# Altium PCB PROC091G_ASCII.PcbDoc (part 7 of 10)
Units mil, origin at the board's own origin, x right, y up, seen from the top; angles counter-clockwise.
Board outline 4538.11 x 994.94 mil, 8 copper layers (Top Layer, GND1, Sig1, PWR1, PWR2, Sig2, GND2, Bottom Layer), stack 59.155 mil thick; 447 components, 329 nets, 5050 pads, 868 vias.
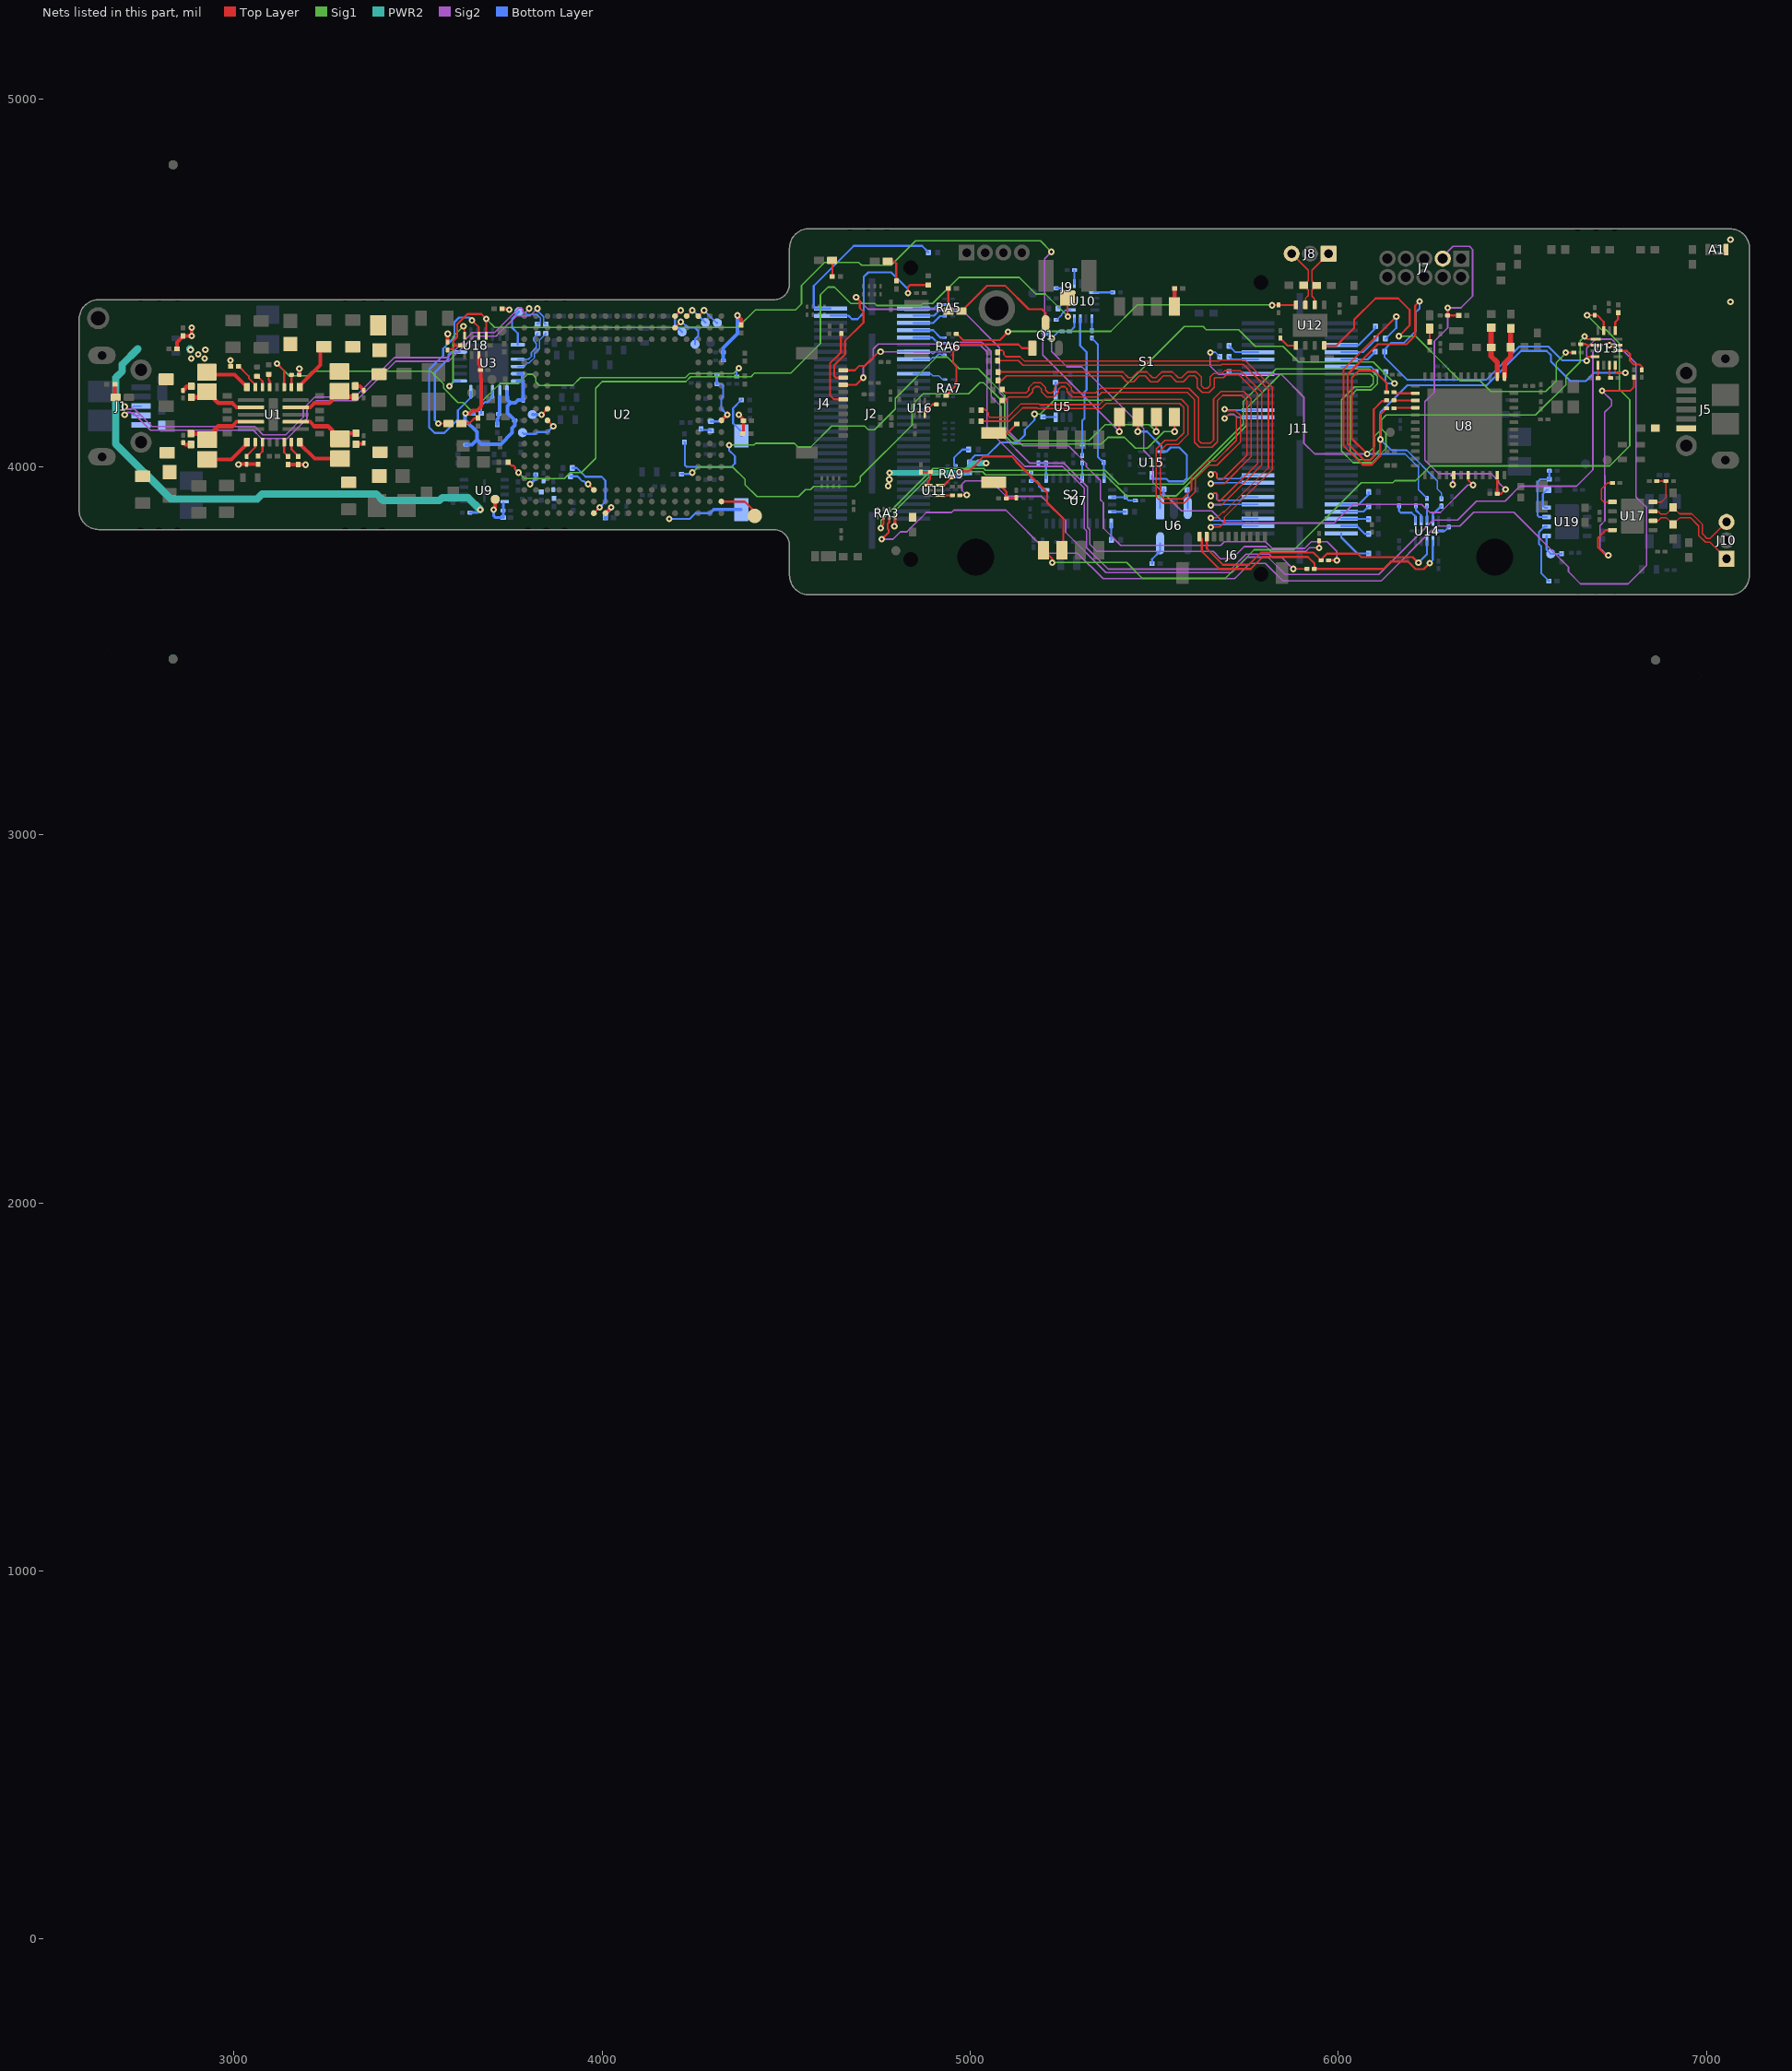
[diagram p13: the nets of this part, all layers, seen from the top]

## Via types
v1: diameter 18, hole 8, Top Layer to Bottom Layer, tented both sides, 832 vias
v2: diameter 19.68, hole 7.87, Top Layer to Bottom Layer, tented both sides, 34 vias
v3: diameter 17, hole 7.87, Top Layer to Bottom Layer, tented both sides, 1 vias
v4: diameter 17, hole 8, Top Layer to Bottom Layer, tented both sides, 1 vias

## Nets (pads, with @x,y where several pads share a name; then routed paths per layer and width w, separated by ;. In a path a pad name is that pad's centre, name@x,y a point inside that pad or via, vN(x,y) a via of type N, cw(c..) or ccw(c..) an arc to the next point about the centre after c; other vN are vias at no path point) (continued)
NetJ2_42: J2.42 RA7.4 | length 92
  Bottom Layer w4: J2.42@4846.16,4252.77 4892.84,4252.77 4898.97,4246.64 4915.49,4246.64 4924.86,4237.27 RA7.4@4931.69,4237.27
NetJ2_46: J2.46 RA6.1 | length 90.9
  Bottom Layer w4: J2.46@4846.16,4292.14 4892.84,4292.14 4897.18,4296.48 4904.46,4296.48 4914.12,4306.15 4919.89,4306.15 4922.26,4303.77 RA6.1@4930.26,4303.77
NetJ2_48: J2.48 RA6.2 | length 90.9
  Bottom Layer w4: J2.48@4846.16,4311.82 4892.84,4311.82 4897.18,4307.48 4899.9,4307.48 4903.44,4311.02 4909.57,4317.15 4919.89,4317.15 4922.26,4319.52 RA6.2@4930.26,4319.52
NetJ2_52: J2.52 RA6.3 | length 90.7
  Bottom Layer w5.5: J2.52@4846.16,4351.19 4897.66,4351.19 4913.58,4335.27 RA6.3@4930.26,4335.27
NetJ2_54: J2.54 RA6.4 | length 92.3
  Bottom Layer w5.5: J2.54@4846.16,4370.88 4899.09,4370.88 4918.95,4351.02 RA6.4@4930.26,4351.02
NetJ2_56: J2.56 RA5.1 | length 92.2
  Bottom Layer w5.5: J2.56@4846.16,4390.56 4899.25,4390.56 4917.78,4409.09 RA5.1@4930.68,4409.09
NetJ2_57: J2.57 R14.1 | length 428.2
  Top Layer w5.5: v1(4831,4471.63) 4831,4488.23 4836.24,4493.46 R14.1@4886,4493.46
  Bottom Layer w5.5: J2.57@4620.57,4410.25 4669.54,4410.25 4678.95,4400.84 4693.94,4400.84 4711.09,4417.99 4711.09,4516 4723.3,4528.21 4785.55,4528.21 4831,4482.76 v1(4831,4471.63)
NetJ2_58: J2.58 RA5.2 | length 90.6
  Bottom Layer w5.5: J2.58@4846.16,4410.25 4901.51,4410.25 4916.1,4424.84 RA5.2@4930.68,4424.84
NetJ2_59: J2.59 R12.1 | length 468.6
  Bottom Layer w5.5: J2.59@4620.57,4429.93 4579.07,4429.93 4575,4434 4575,4491 4684.01,4600.01 4869.23,4600.01 4886.18,4583.06 R12.1@4886.18,4582.07
NetJ2_60: J2.60 RA5.3 | length 88.9
  Bottom Layer w5.5: J2.60@4846.16,4429.93 4901.9,4429.93 4912.56,4440.59 RA5.3@4930.68,4440.59
NetJ4_1: J4.1 R185.2 | length 1787
  Top Layer w4.2: v1(5877.52,3722.34) 5877.68,3722.49 R185.2@5915.32,3722.49
  Top Layer w5.5: J4.1@4655.33,4261.92 4686.74,4261.92 4699.09,4274.27 4713.5,4274.27 4751.62,4312.39 v1(4756.43,4312.39)
  Sig2 w4.2: v1(4756.43,4312.39) 4945.94,4312.39 4963.54,4329.99 5028.14,4329.99 5046.11,4312.02 5046.11,4103.61 5148.58,4001.15 5251.09,4001.15 5310.09,3942.14 5310.09,3831.93 5316.31,3825.72 5316.31,3780.32 5374.82,3721.81 5708.67,3721.81 5749.48,3762.62 5812.52,3762.62 5820.92,3754.22 5845.64,3754.22 v1(5877.52,3722.34)
NetJ4_2: J4.2 R184.2 | length 2138.7
  Top Layer w5.5: J4.2@4655.33,4242.23 4634.63,4242.23 4630.69,4246.17 4630.69,4275.86 4660.18,4305.35 4660.18,4341.86 4710,4391.68 4710,4421.45 4700,4431.45 4700,4450.56 v1(4690.34,4460.22) ; R184.2@5973.37,3745.98 v1@5996.22,3745.98
  Sig2 w4.2: v1(4690.34,4460.22) 4722.61,4427.95 4975.45,4427.95 5080.01,4323.39 5080.01,4201.21 5100.76,4180.46 5100.76,4099.49 5143.46,4056.79 5267.6,4056.79 5315.85,4008.55 5315.85,4000.78 5353.67,3962.95 5353.67,3910.52 5362.07,3902.12 5362.07,3833.36 5408.84,3786.59 5680.29,3786.59 5690.37,3796.67 5802.23,3796.67 5820.8,3778.11 5908.27,3778.11 5926.79,3796.63 5970.1,3796.63 5996.34,3770.38 v1(5996.34,3745.86)
NetJ4_3: J4.3 R183.2 | length 1860.1
  Top Layer w5.5: J4.3@4655.33,4222.55 4690.14,4222.55 v1(4709.72,4242.13) ; v1(5947.68,3779.72) R183.2@5947.68,3798.4
  Sig2 w4.2: v1(4709.72,4242.13) 4709.72,4269.52 4736.36,4296.16 4736.36,4319.64 4750.21,4333.49 4955.16,4333.49 4960.06,4338.39 5031.61,4338.39 5056.94,4313.07 5056.94,4190.97 5083.96,4163.95 5083.96,4087.47 5161.87,4009.55 5254.56,4009.55 5318.49,3945.62 5318.49,3835.41 5324.71,3829.2 5324.71,3789.37 5344.29,3769.79 5660.31,3769.79 5680.02,3750.08 5711.21,3750.08 5744.21,3783.09 5803.94,3783.09 5817.32,3769.71 5911.75,3769.71 5921.77,3779.72 v1(5947.68,3779.72)
NetJ4_5: J4.5 R182.2 | length 220.1
  Top Layer w5.5: R182.2@4650.14,4360.81 4648.68,4359.35 4648.68,4310.11 4619.19,4280.63 4619.19,4194.32 4630.34,4183.18 J4.5@4655.33,4183.18
NetJ8_1: J8.1 R126.1 U12.6 | length 171.7
  Top Layer w4: U12.6@5936.23,4439.58 5936.23,4455.71 5928.49,4463.46 5928.49,4479.74 R126.1@5941.23,4492.48 5928.49,4505.23 5928.49,4533.93 J8.1@5973.44,4578.88
NetJ8_3: J8.3 R119.2 U12.7 | length 171.7
  Top Layer w4: J8.3@5873.44,4578.88 5918.39,4533.93 5918.39,4505.52 R119.2@5905.64,4492.77 5918.39,4480.03 5918.39,4464.68 5910.64,4456.94 U12.7@5910.64,4439.58
NetJ9_1: J9.1 R109.2 | length 2093.9
  Top Layer w5.5: R109.2@3744.93,4012.38 3754.32,4003 3759.5,4003 3763.64,3998.86 3763.64,3993.5 v1(3773.02,3984.13) ; J9.1@5264.12,4458.32 5264.12,4409.45 v1(5265.4,4408.17)
  Sig1 w4.2: v1(3773.02,3984.13) 3789.15,3968 3897.5,3968 3913.75,3984.25 3944.25,3984.25 3982.78,4022.78 3982.78,4213.56 4000.43,4231.21 4227.66,4231.21 4241.04,4244.59 4404.59,4244.59 4414.28,4254.28 4512.93,4254.28 4593,4334.35 4593,4467 4614,4488 4631.2,4488 4675.95,4443.25 4740.74,4443.25 4745.91,4438.08 4865.87,4438.08 4871.09,4443.3 4898.45,4443.3 4969.66,4514.51 5133.53,4514.51 5178.56,4469.48 5204.09,4469.48 v1(5265.4,4408.17)
NetJ10_1: J10.1 R117.1 U17.6 | length 279.7
  Top Layer w4: U17.6@6854.9,3853.2 6868.71,3853.2 6876.46,3860.95 6891.92,3860.95 R117.1@6909.66,3843.2 6928.28,3861.82 6956.61,3861.82 6979.41,3839.02 6979.41,3813.1 6997.56,3794.95 7009.86,3794.95 J10.1@7054.81,3750
NetJ10_3: J10.3 R114.2 U17.7 | length 279.6
  Top Layer w4: U17.7@6854.9,3878.8 6868.71,3878.8 6876.46,3871.05 6891.02,3871.05 R114.2@6909.57,3889.61 6927.26,3871.92 6934.39,3871.92 6960.79,3871.92 6989.51,3843.2 6989.51,3817.28 7001.74,3805.05 7009.86,3805.05 J10.3@7054.81,3850
NetJ11_7: J11.7 R150.1 | length 117.4
  Bottom Layer w5.5: J11.7@6007.91,4330.88 6055.82,4330.88 6100.82,4375.88 R150.1@6100.82,4381.76
NetJ11_9: J11.9 R151.1 | length 111.5
  Bottom Layer w5.5: J11.9@6007.91,4311.19 6067.59,4311.19 6102.62,4346.22 R151.1@6102.62,4348.48
NetJ11_10: J11.10 R152.2 | length 85.7
  Bottom Layer w5.5: R152.2@5703.72,4328.4 5720.93,4311.19 J11.10@5782.32,4311.19
NetJ11_11: J11.11 R153.1 | length 101.3
  Bottom Layer w5.5: J11.11@6007.91,4291.51 6079.44,4291.51 R153.1@6100.53,4312.59
NetJ11_12: J11.12 R154.2 | length 81.7
  Bottom Layer w5.5: R154.2@5703.72,4298.93 5711.14,4291.51 J11.12@5782.32,4291.51
NetJ11_13: J11.13 R155.1 | length 100.7
  Bottom Layer w5.5: J11.13@6007.91,4271.82 6088.51,4271.82 R155.1@6102.76,4257.57
NetJ11_16: J11.16 R157.2 | length 80.9
  Bottom Layer w5.5: R157.2@5703.72,4257.72 5709.31,4252.14 J11.16@5782.32,4252.14
NetJ11_26: J11.26 R142.2 | length 1406.7
  Top Layer w4: R142.2@5029.87,4123.69 5106.17,4123.69 5142.59,4160.12 5181.65,4160.12 5183.99,4157.77 5355.15,4157.77 5369.44,4172.06 5569.36,4172.06 5580.3,4161.12 5580.3,4091.79 5560.01,4071.51 5529.19,4071.51 5505.39,4047.7 5505.39,3918.62 5522.21,3901.79 5581.54,3901.79 5612.17,3932.43 5612.17,3967.43 5648.64,4003.9 5670.59,4003.9 5734.2,4067.51 5734.2,4139.44 5722.14,4151.51 5696.52,4151.51 v1(5691.66,4156.37)
  Bottom Layer w4: v1(5691.66,4156.37) 5694.31,4153.71 J11.26@5782.32,4153.71
NetJ11_28: J11.28 R143.2 | length 1394.2
  Top Layer w4: R143.2@5029.87,4153.69 5033.06,4156.88 5038.48,4156.88 5048.87,4146.48 5048.87,4138.92 5053.1,4134.69 5101.61,4134.69 5129.25,4162.33 5138.04,4171.12 5186.2,4171.12 5188.55,4168.77 5350.59,4168.77 5364.88,4183.06 5573.92,4183.06 5591.3,4165.68 5591.3,4087.24 5564.57,4060.51 5533.75,4060.51 5516.39,4043.14 5516.39,3923.17 5526.77,3912.79 5576.98,3912.79 5601.17,3936.98 5601.17,3971.98 5644.09,4014.9 5666.03,4014.9 5723.2,4072.07 5723.2,4134.89 5717.58,4140.51 5700.79,4140.51 v1(5691.66,4131.37)
  Bottom Layer w4: v1(5691.66,4131.37) 5703,4142.71 5717.1,4142.71 5725.78,4134.03 J11.28@5782.32,4134.03
NetJ11_44: J11.44 R144.2 | length 1442.9
  Top Layer w4: R144.2@5087.73,4180.12 5090.98,4176.88 5096.57,4176.88 5101.19,4181.5 5101.19,4185.67 5105.14,4189.62 5156.29,4189.62 5170.01,4203.34 5170.01,4210.43 5177.29,4217.71 5186.73,4217.71 5194.01,4210.43 5194.01,4203.34 5207.73,4189.62 5226.29,4189.62 5240.01,4203.34 5240.01,4210.43 5247.29,4217.71 5256.73,4217.71 5264.01,4210.43 5264.01,4203.34 5277.73,4189.62 5345.19,4189.62 5357.68,4202.11 5589.59,4202.11 5609.3,4182.4 5609.3,4066.81 5623.19,4052.92 5657.16,4052.92 5672.13,4067.89 5672.13,4179.83 5686.05,4193.75 5738.48,4193.75 5752.25,4179.98 5752.25,4031.61 5685.85,3965.2 5673.82,3965.2 5669.23,3969.8 5669.23,3982.18 5665.52,3985.9 5660.36,3985.9 v1(5653.67,3979.2)
  Bottom Layer w4: v1(5653.67,3979.2) 5660.23,3985.77 5665.46,3985.77 5669.23,3982 5669.23,3971.01 5672.38,3967.86 5732.95,3967.86 5741.64,3976.55 J11.44@5782.32,3976.55
NetJ11_46: J11.46 R145.2 | length 1436.5
  Top Layer w4: R145.2@5087.73,4210.12 5097.23,4200.62 5151.73,4200.62 5159.01,4207.9 5159.01,4214.99 5172.73,4228.71 5191.29,4228.71 5205.01,4214.99 5205.01,4207.9 5212.29,4200.62 5221.73,4200.62 5229.01,4207.9 5229.01,4214.99 5242.73,4228.71 5261.29,4228.71 5275.01,4214.99 5275.01,4207.9 5282.29,4200.62 5340.63,4200.62 5353.12,4213.11 5594.15,4213.11 5620.3,4186.96 5620.3,4071.37 5627.75,4063.92 5652.6,4063.92 5661.13,4072.45 5661.13,4184.38 5681.5,4204.75 5743.04,4204.75 5763.25,4184.53 5763.25,4102.24 5763.25,4035.73 5763.25,4027.05 5690.4,3954.2 v1(5653.67,3954.2)
  Bottom Layer w4: v1(5653.67,3954.2) 5656.32,3956.86 J11.46@5782.32,3956.86
NetJ11_50: J11.50 R146.2 | length 1368.9
  Top Layer w4: R146.2@5075.6,4234.19 5086.07,4234.19 5098.59,4246.71 5409.93,4246.71 5425.53,4231.1 5444.09,4231.1 5459.69,4246.71 5475.03,4246.71 5490.63,4231.1 5509.19,4231.1 5524.79,4246.71 5545.03,4246.71 5560.63,4231.1 5579.19,4231.1 5594.79,4246.71 5609.63,4246.71 5616.91,4239.43 5616.91,4215.8 5630.63,4202.08 5649.19,4202.08 5662.91,4215.8 5662.91,4239.43 5665.41,4241.93 5688.02,4241.93 5695.55,4249.45 5729.88,4249.45 5781.25,4198.09 5781.25,4009.36 5678.04,3906.15 5675.38,3906.15 5671.19,3910.34 5671.19,3925.66 5667.88,3928.97 5662.49,3928.97 v1(5653.67,3920.15)
  Bottom Layer w4: v1(5653.67,3920.15) 5661.55,3928.03 5666.72,3928.03 5670.05,3924.7 5670.05,3911.67 5672.92,3908.81 5732.93,3908.81 5741.61,3917.49 J11.50@5782.32,3917.49
NetJ11_51: J11.51 R186.1 | length 92.4
  Bottom Layer w5.5: J11.51@6007.91,3897.81 6055.77,3897.81 6082.75,3924.78 R186.1@6082.75,3931.22
NetJ11_52: J11.52 R147.2 | length 1357
  Top Layer w4: R147.2@5075.6,4257.19 5076.11,4257.71 5414.49,4257.71 5430.09,4242.1 5439.53,4242.1 5455.13,4257.71 5479.59,4257.71 5495.19,4242.1 5504.63,4242.1 5520.24,4257.71 5549.59,4257.71 5565.19,4242.1 5574.63,4242.1 5590.24,4257.71 5614.19,4257.71 5627.91,4243.98 5627.91,4220.35 5635.19,4213.08 5644.63,4213.08 5651.91,4220.35 5651.91,4243.98 5660.85,4252.93 5683.47,4252.93 5690.99,4260.45 5734.44,4260.45 5792.25,4202.64 5792.25,4004.8 5682.6,3895.15 v1(5653.67,3895.15)
  Bottom Layer w4: v1(5653.67,3895.15) 5656.32,3897.81 J11.52@5782.32,3897.81
NetJ11_53: J11.53 R187.1 | length 80.7
  Bottom Layer w5.5: J11.53@6007.91,3878.12 6068.61,3878.12 R187.1@6082.75,3892.26
NetJ11_55: J11.55 R188.1 | length 75.3
  Bottom Layer w5.5: J11.55@6007.91,3858.44 6081.73,3858.44 R188.1@6082.75,3857.41
NetJ11_56: J11.56 R148.2 | length 1329.7
  Top Layer w4: R148.2@5074.9,4288.03 5131.05,4288.03 5143.37,4275.71 5680.79,4275.71 5683.54,4278.45 5741.9,4278.45 5809.44,4210.91 5810.25,4210.91 5810.25,3997.34 5690.06,3877.15 5686.48,3877.15 5670.22,3860.89 v1@5653.67,3860.89
  Bottom Layer w4: v1(5653.67,3861.09) 5660.76,3854 5737.2,3854 5741.64,3858.44 J11.56@5782.32,3858.44
NetJ11_57: J11.57 R189.1 | length 83.6
  Bottom Layer w5.5: J11.57@6007.91,3838.75 6050.7,3838.75 6071.89,3817.56 R189.1@6082.75,3817.56
NetJ11_58: J11.58 R149.2 | length 1393.6
  Top Layer w4: R149.2@5074.9,4311.03 5080.34,4316.47 5087.21,4316.47 5091.52,4312.15 5091.52,4304.45 5096.94,4299.03 5135.6,4299.03 5147.92,4286.71 5676.23,4286.71 5678.98,4289.45 5746.45,4289.45 5814,4221.91 5814.81,4221.91 5821.25,4215.46 5821.25,3992.79 5690.22,3861.76 5690.22,3848.29 5678.03,3836.09 v1(5653.67,3836.09)
  Bottom Layer w4: v1(5653.67,3836.09) 5660.57,3843 5737.76,3843 5742,3838.75 J11.58@5782.32,3838.75
NetJ11_59: J11.59 R190.1 | length 103.7
  Bottom Layer w5.5: J11.59@6007.91,3819.07 6007.91,3808.41 6051.8,3764.53 R190.1@6082.75,3764.53
NetLD1_1: LD1.1 R39.2 | length 36.4
  Top Layer w10: R39.2@2676.69,4224 2676.69,4190.75 LD1.1@2678.94,4188.5
NetLD2_1: LD2.1 R13.2 | length 45.6
  Top Layer w5.5: R13.2@4625.39,4516.76 4625.39,4559.66 LD2.1@4627.29,4561.55
NetLD3_2: LD3.2 R42.1 | length 70.9
  Top Layer w5.5: LD3.2@4777.82,4558.15 4793.46,4558.15 4799.25,4552.36 R42.1@4799.25,4505.25
NetLD4_1: LD4.1 U3.17 | length 268.7
  Top Layer w5.5: v1(3555.07,4117.07) LD4.1@3582.28,4117.07
  Bottom Layer w5.5: v1(3555.07,4117.07) 3545.55,4126.6 3545.55,4256.3 3582.49,4293.24 3582.49,4304.56 3589.66,4311.72 U3.17@3614.31,4311.72
NetLD4_2: LD4.2 R15.2 | length 51.7
  Top Layer w5.5: LD4.2@3617.72,4117.07 3618.77,4118.12 3639.5,4118.12 3653.89,4132.51 R15.2@3663,4132.51
NetLD5_1: LD5.1 R107.2 | length 62.2
  Top Layer w5.5: R107.2@4940.62,4484.7 4940.62,4422.78 LD5.1@4940.84,4422.56
NetLD5_2: LD5.2 Q1.3 | length 314.8
  Top Layer w5.5: LD5.2@4976.27,4422.56 5045.24,4491.53 5095.52,4491.53 5159.02,4428.03 5195.6,4428.03 5205.08,4418.55 Q1.3@5205.08,4391.38
NetLD6_1: LD6.1 R17.2 | length 36.5
  Top Layer w5.5: R17.2@6248.18,4339.19 LD6.1@6248.18,4375.65
NetQ1_1: Q1.1 R108.2 | length 360.6
  Top Layer w5.5: R108.2@4935.02,4194 4958.98,4217.95 4958.98,4228.46 4962.49,4231.98 4962.49,4272.81 4954.04,4281.26 4954.04,4312.57 4973.59,4332.12 5131.19,4332.12 5140.96,4322.35 Q1.1@5169.06,4322.35
NetR2_2: R2.2 R174.1 | length 30.8
  Bottom Layer w5.5: R174.1@4267.1,4102.78 4269.74,4100.14 4293.06,4100.14 R2.2@4295.7,4097.5
NetR16_2: R16.2 S1.5 | length 49
  Top Layer w12: S1.5@5555.37,4435.46 R16.2@5555.37,4484.46
NetR20_2: R20.2 R29.2 U19.3 | length 175.3
  Bottom Layer w5.5: U19.3@6566.06,3863.26 6545.65,3863.26 6541.75,3867.15 6541.75,3959.03 6548.66,3965.94 R29.2@6573.16,3965.94 6573.41,3966.19 6573.41,3988.69 R20.2@6573.66,3988.94
NetR24_2: R24.2 U19.4 | length 62
  Bottom Layer w5.5: U19.4@6566.91,3888.6 6561.61,3888.6 6556.06,3894.15 6556.06,3926.09 6567.43,3937.46 R24.2@6568.28,3937.46
NetR27_2: R27.2 TP10.1 U19.1 | length 82.5
  Bottom Layer w5.5: U19.1@6566.06,3812.08 6566.06,3774.58 TP10.1@6577.18,3763.46 6606.29,3763.46 R27.2@6606.39,3763.57
NetR30_2: R30.2 U10.10 | length 42
  Bottom Layer w4.2: R30.2@5238.8,4430 5238.8,4430.98 5249.67,4441.85 U10.10@5275.3,4441.85
NetR40_2: R40.2 U3.9 | length 75.4
  Bottom Layer w5.5: R40.2@3671.81,4145.37 3671.81,4165.8 3681.85,4175.84 3689.03,4175.84 3702.45,4189.27 U3.9@3702.49,4203.87
NetR41_1: R41.1 U3.3 | length 115.3
  Bottom Layer w4: U3.3@3770.97,4292.04 3800.14,4292.04 3808.12,4300.03 3808.12,4311.17 3821.34,4324.39 3821.34,4334.97 3814.23,4342.08 3814.23,4350.59 3825.31,4361.66 R41.1@3825.31,4361.83
NetR51_2: R51.2 U5.1 | length 36.2
  Bottom Layer w5.5: R51.2@5232,4229 5232.15,4228.85 5232.15,4193.05 U5.1@5232.29,4192.9
NetR57_2: R57.2 U5.6 | length 34.4
  Bottom Layer w5.5: R57.2@5198,4135 5231.92,4135 U5.6@5232.29,4134.63
NetR58_2: R58.2 RA9.5 | length 72.9
  Bottom Layer w5.5: RA9.5@4960.68,4003.38 4959.62,4003.38 4956,4007 4956,4024 4978.94,4046.94 R58.2@4996.2,4046.94
NetR60_1: R60.1 U3.4 | length 133.5
  Bottom Layer w4: U3.4@3770.97,4272.35 3788.06,4272.35 3798.3,4282.59 3802.71,4282.59 3816.62,4296.51 3816.62,4307.65 3829.84,4320.87 3829.84,4344.29 3846.82,4361.26 R60.1@3846.82,4361.83
NetR61_1: R61.1 U2.G1 | length 205.4
  Top Layer w5.5: U2.G1@3977.74,3873.89 v1(3993.49,3889.64)
  Bottom Layer w5.5: R61.1@3919.26,3996.54 3931.16,3996.54 3955.07,3972.62 3998.69,3972.62 4009.14,3962.18 4009.14,3905.29 v1(3993.49,3889.64)
NetR62_1: R62.1 U2.G3 | length 78.7
  Top Layer w5.5: v1(3961.99,3952.63) U2.G3@3977.74,3936.89
  Bottom Layer w5.5: R62.1@3914.33,3973.85 3933.23,3973.85 3946.51,3960.57 3950.67,3960.57 3958.61,3952.63 v1(3961.99,3952.63)
NetR66_2: R66.2 R122.1 U12.8 | length 969.6
  Top Layer w5.5: R66.2@4962.39,4360.97 4964.19,4360.97 4980.89,4344.27 5080.77,4344.27 v1(5102.88,4366.38) ; v1(5819.95,4438.8) 5820.74,4439.58 R122.1@5837.64,4439.58 U12.8@5885.05,4439.58
  Sig1 w4.2: v1(5102.88,4366.38) 5104.17,4367.67 5382.03,4367.67 5453.86,4439.5 5819.25,4439.5 v1(5819.95,4438.8)
NetR67_2: R67.2 U6.1 | length 55.2
  Bottom Layer w5.5: U6.1@5516.13,3887.87 5516.13,3918.5 5526.13,3928.5 R67.2@5526.13,3938.91
NetR68_2: R68.2 U6.3 | length 51
  Bottom Layer w5.5: U6.3@5590.94,3887.87 R68.2@5590.94,3938.91
NetR69_2: R69.2 U6.5 | length 64.2
  Bottom Layer w5.5: R69.2@5494.09,3737.11 5494.09,3748.66 5516.13,3770.71 U6.5@5516.13,3792.16
NetR70_1: R70.1 U7.19 | length 35.3
  Bottom Layer w5.5: U7.19@5385.92,3877.69 R70.1@5421.2,3877.69
NetR71_1: R71.1 U7.20 | length 44.4
  Bottom Layer w5.5: R71.1@5383.46,3801.26 U7.20@5383.46,3845.7
NetR72_2: R72.2 R73.2 U7.17 | length 67.9
  Bottom Layer w5.5: U7.17@5385.92,3917.06 5386,3917.14 5422.68,3917.14 R72.2@5422.76,3917.23 5422.76,3915.43 5430.18,3908 R73.2@5448.84,3908
NetR74_2: R74.2 U11.4 | length 66.9
  Top Layer w4.2: U11.4@4918.45,3921.94 4918.95,3922.44 R74.2@4951.69,3922.44 4951.19,3921.94 4948.22,3921.94 U11.4@4918.45,3921.94
NetR76_1: R76.1 U14.8 | length 47.5
  Bottom Layer w5.5: R76.1@6210.78,3892.42 6210.78,3882.19 6225.29,3867.67 U14.8@6225.29,3852.92 U14.8@6225.29,3850.95
NetR79_1: R79.1 U14.12 | length 32.5
  Bottom Layer w5.5: U14.12@6272.54,3825.36 6289.39,3825.36 R79.1@6300.48,3836.45
NetR86_2: R86.2 U8.15 | length 58.7
  Top Layer w5.5: R86.2@6151.04,4180.57 6151.61,4180.01 U8.15@6209.52,4180.01
NetR87_2: R87.2 U8.14 | length 59.5
  Top Layer w5.5: R87.2@6151.19,4202.46 6153.97,4199.69 U8.14@6209.52,4199.69
NetR92_1: R92.1 U19.2 | length 170.9
  Bottom Layer w5.5: U19.2@6566.06,3837.67 6560.18,3837.67 6545.5,3822.99 6545.5,3789.79 6551.18,3784.11 6551.18,3710.76 R92.1@6572.2,3689.74
NetR97_1: R97.1 U7.11 | length 41.7
  Bottom Layer w5.5: U7.11@5304.72,3968.74 R97.1@5304.72,4010.48
NetR99_1: R99.1 U10.12 | length 46.8
  Bottom Layer w5.5: R99.1@5233.31,4485 5246.87,4485 5258.52,4473.35 U10.12@5275.3,4473.35
NetR100_2: R100.2 U10.5 | length 32.7
  Bottom Layer w5.5: U10.5@5330.42,4402.48 5330.71,4402.2 5330.71,4370.31 R100.2@5331,4370.02
NetR101_1: R101.1 U10.13 | length 37.4
  Bottom Layer w5.5: U10.13@5283.18,4496.97 R101.1@5283.18,4534.36
NetR105_1: R105.1 R106.1 U11.1 | length 64.2
  Top Layer w5.5: R105.1@4865.78,3985.56 4891.33,3985.56 4891.33,3966.85 4884.99,3960.5 U11.1@4884.99,3949.5
NetR111_1: R111.1 SW3.2 | length 87.5
  Top Layer w5.5: SW3.2@5051.37,4086.32 5096.23,4086.32 R111.1@5126.37,4116.46
NetR112_2: R112.2 U10.8 | length 41.8
  Bottom Layer w5.5: R112.2@5269.37,4367.46 5271.17,4367.46 5283.18,4379.47 U10.8@5283.18,4402.48
NetR113_2: R113.2 U10.9 | length 51.8
  Bottom Layer w4.2: R113.2@5233.31,4399 5235.11,4399 5248.25,4412.14 5248.25,4415.2 5258.32,4425.27 U10.9@5272.48,4425.27
NetR115_2: R115.2 R134.1 U17.8 | length 109.7
  Top Layer w4: U17.8@6854.9,3904.39 6878.17,3904.39 6889.78,3916 R134.1@6889.78,3961 R115.2@6864.81,3961
NetR116_1: R116.1 U17.1 | length 98.1
  Top Layer w4: U17.1@6744.66,3904.39 6721.39,3904.39 6714.78,3911 6714.78,3939.82 6730.96,3956 R116.1@6744.78,3956
NetR120_1: R120.1 U17.4 | length 710.9
  Top Layer w5.5: v1(6716.81,4206) 6792.81,4206 6802.81,4216 R120.1@6802.81,4242.98 ; v1@6734.81,3758 v1(6733.81,3759) 6727.34,3759 6705.81,3780.52 6705.81,3807.03 6726.4,3827.61 U17.4@6744.66,3827.61
  Sig2 w4.2: v1(6716.81,4206) 6742.2,4180.61 6742.2,4166.17 6724.03,4148 6724.03,3976.36 6724.35,3976.04 6724.35,3853.19 6711.4,3840.24 6711.4,3778.41 6730.8,3759 v1(6733.81,3759)
NetR121_1: R121.1 U13.2 | length 39.5
  Top Layer w5.5: R121.1@6659.06,4333.23 6671.58,4333.23 6674.18,4330.63 U13.2@6697.44,4330.63
NetR123_1: R123.1 U12.1 | length 51.4
  Top Layer w5.5: R123.1@5843.14,4349.69 5843.14,4347.89 5861.69,4329.34 U12.1@5885.05,4329.34
NetR125_2: R125.2 R129.1 SW3.1 | length 103.2
  Top Layer w5.5: SW3.1@5051.37,3952.46 5063.87,3952.46 5077.69,3952.46 5098.17,3931.98 R125.2@5098.17,3914.04 5123.33,3914.04 R129.1@5125.2,3915.92 ; R129.1@5123.7,3917.42 R129.1@5125.2,3918.92
NetR127_1: R127.1 U12.4 | length 1006.3
  Top Layer w5.5: U12.4@5961.82,4329.34 5995.51,4329.34 6042.85,4376.69 6042.85,4399.01 6101.34,4457.5 6162.59,4457.5 6194.07,4426.03 6194.07,4383.99 v1(6164.91,4354.84) ; v1(6617.81,4310) R127.1@6639.79,4310
  Sig1 w4.2: v1(6164.91,4354.84) 6210.29,4354.84 6298.55,4266.58 6298.55,4266.12 6307.51,4257.15 6307.97,4257.15 6332.04,4233.09 6385.37,4233.09 6414.32,4204.14 6563.45,4204.14 6591.91,4232.6 6591.91,4282.7 6617.81,4308.6 v1(6617.81,4310)
NetR128_1: R128.1 U13.5 | length 35
  Top Layer w5.5: U13.5@6705.32,4275.51 6705.32,4241.13 R128.1@6705.74,4240.71
NetR131_2: R131.2 U8.29 | length 53.8
  Top Layer w5.5: v1(6311.16,3951.46) 6313.85,3954.16 U8.29@6313.85,3977.25
  Bottom Layer w5.5: v1(6311.16,3951.46) R131.2@6311.16,3978.41
NetR136_1: R136.1 U13.7 | length 35.8
  Top Layer w5.5: U13.7@6736.81,4275.51 6736.81,4244 R136.1@6739.81,4241
NetR139_1: R139.1 U13.10 | length 104.2
  Top Layer w5.5: U13.10@6760.43,4314.88 6783.81,4314.88 6792.31,4306.38 6792.31,4288.27 6802.86,4277.72 6819.09,4277.72 6824.81,4272 R139.1@6824.81,4263 R139.1@6823.09,4264.72
NetR141_1: R141.1 U13.13 | length 51.3
  Top Layer w5.5: U13.13@6752.56,4370 6752.56,4392.75 6760.03,4400.22 R141.1@6760.03,4418.23
NetR160_1: R160.1 U14.10 | length 52.7
  Bottom Layer w5.5: U14.10@6256.79,3850.95 6256.79,3870.7 6256.89,3870.7 6278.3,3892.11 6278.3,3892.21 6279.35,3893.26 R160.1@6280.34,3893.26
NetR161_2: R161.2 U8.16 | length 59.1
  Top Layer w5.5: R161.2@6151.19,4158.46 6153.05,4160.32 U8.16@6209.52,4160.32
NetR166_1: R166.1 U14.9 | length 41.8
  Bottom Layer w5.5: R166.1@6240.62,3892.57 6240.62,3851.38 U14.9@6241.04,3850.95
NetR168_1: R168.1 U14.7 | length 77.4
  Bottom Layer w5.5: R168.1@6165.24,3892.54 6165.24,3879.64 6169.52,3875.36 6199.32,3875.36 6209.55,3865.14 U14.7@6209.55,3852.92 U14.7@6209.55,3850.95
NetR176_1: R176.1 S3.1 | length 117
  Bottom Layer w5.5: S3.1@4378.33,4083.66 4378.33,4095.26 4355.69,4117.91 4355.69,4158.92 R176.1@4378.58,4181.8
NetR178_2: R178.2 U16.3 | length 44.7
  Top Layer w5.5: U16.3@4877.15,4143.71 4877.15,4148.84 4897.78,4169.46 R178.2@4908.17,4169.46
NetTP2_1: TP2.1 U2.C10 | length 47.8
  Top Layer w5.5: v1(3836.01,4141.61) U2.C10@3851.76,4157.36
  Bottom Layer w8: TP2.1@3810.59,4141.77 3835.85,4141.77 v1(3836.01,4141.61)
NetTP3_1: TP3.1 U2.C9 | length 115.7
  Top Layer w5.5: U2.C9@3851.76,4125.86 v1(3867.5,4110.11)
  Bottom Layer w5.5: TP3.1@3784,4092.76 3787.31,4089.45 3818.58,4089.45 3823.59,4094.46 3851.85,4094.46 v1(3867.5,4110.11)
NetTP6_1: TP6.1 U2.T18 | length 72.5
  Top Layer w5.5: U2.T18@4261.2,4409.33 v1(4276.95,4425.07)
  Bottom Layer w5.5: v1(4276.95,4425.07) 4311.08,4390.94 TP6.1@4313,4390.94
NetTP7_1: TP7.1 U2.R18 | length 71.4
  Top Layer w5.5: U2.R18@4229.71,4409.33 v1(4245.46,4425.07)
  Bottom Layer w5.5: v1(4245.46,4425.07) 4247.21,4425.07 TP7.1@4280.69,4391.59
NetTP8_1: TP8.1 U2.P17 | length 119.4
  Top Layer w5.5: U2.P17@4198.21,4377.83 v1(4213.96,4393.58)
  Bottom Layer w5.5: v1(4213.96,4393.58) 4217.13,4393.58 4232.89,4377.82 4251.98,4377.82 4261.2,4368.6 4261.2,4355.69 4252.7,4347.19 TP8.1@4252.7,4332.6
NetTP9_1: TP9.1 U2.P18 | length 95.6
  Top Layer w5.5: U2.P18@4198.21,4409.33 v1(4213.96,4425.07)
  Bottom Layer w5.5: v1(4213.96,4425.07) 4198.22,4409.33 4198.22,4385.27 TP9.1@4217.3,4366.19
NetTP11_1: TP11.1 U2.V2 | length 114.7
  Top Layer w5.5: U2.V2@4324.2,3905.39 4387.61,3905.39 4414.85,3878.15 TP11.1@4414.85,3865.34
NetTP26_1: TP26.1 U3.1 | length 104.7
  Bottom Layer w5.5: U3.1@3770.97,4331.41 3770.97,4362.04 3755.27,4377.75 3755.27,4402.47 TP26.1@3774.42,4421.63
nRESET: C37.1 J7.3 R89.1 R91.1 U8.35 | length 1131.4
  Top Layer w5.5: v1(6297.21,4431.94) C37.1@6297.21,4411.08 R89.1@6327.17,4411.08 ; U8.35@6431.96,3977.25 R91.1@6431.96,3926.46 6442.24,3926.46 v1(6454.22,3938.44)
  Sig2 w4.2: J7.3@6283.84,4565.56 6283.84,4571.36 6311.29,4598.81 6356.39,4598.81 6364.99,4590.21 6364.99,4463.29 6333.64,4431.94 v1(6297.21,4431.94) 6297.21,4377.21 6261.11,4341.11 6261.11,4202.37 6235.7,4176.96 6235.7,4018.3 6273,3981 6415.52,3981 6435.98,3960.55 6435.98,3956.69 v1(6454.22,3938.44)
PGOOD: R31.1 R37.2 R155.2 RA9.7 | length 1511.8
  Sig1 w4.2: v1(5174.61,4143.12) 5190.39,4143.12 5228.25,4180.98 5381.84,4180.98 5581.56,4380.7 5632.92,4380.7 5641.32,4372.3 5729.27,4372.3 5774.35,4327.22 5849.47,4327.22 5892.09,4284.6 6094.72,4284.6 v1(6152.73,4226.59)
  Bottom Layer w5.5: RA9.7@4960.68,3971.89 4961.37,3972.58 4970.57,3972.58 4974.12,3976.14 4978.8,3976.14 4982,3979.33 4994.2,3979.33 R37.2@4998.2,3983.33 R31.1@4998.2,4008 ; R31.1@4998.08,4011.31 4998.08,4015.67 5013.73,4031.31 5047.43,4031.31 5082.59,4066.47 5128.7,4066.47 5148.34,4086.12 5148.34,4100.85 5174.61,4127.11 v1(5174.61,4143.12) ; R155.2@6128.35,4257.57 6128.35,4230.91 6132.67,4226.59 v1(6152.73,4226.59)
PMIC_1V0: C46.1 C111.1 C113.1 L4.1 L12.1 L14.1 L15.1 U1.1 | length 132.5
  Top Layer w10: U1.1@3178.85,4216.41 3178.85,4220.35 3234.4,4275.9 C113.1@3234.4,4325.91
PMIC_1V2: C45.1 C112.1 L3.1 L13.1 U1.14 | length 129.5
  Top Layer w10: L3.1@2927.23,4020.16 2992.44,4020.16 3035.15,4062.87 U1.14@3035.15,4066.81
PMIC_1V8: C47.1 C121.1 L5.1 L11.1 U1.21 | length 130.1
  Top Layer w10: U1.21@3178.85,4066.81 3178.85,4062.87 3219.43,4022.29 L5.1@3288.17,4022.29
PMIC_3V3: C2.2 C3.2 C44.1 C87.1 C88.1 C100.1 C101.1 C102.1 C126.1 FL22.1 L2.1 R2.1 R4.1 R5.1 R7.2 R8.2 R9.1 R19.2 R21.2 R22.2 R23.2 R31.2 R40.1 R43.2 R44.2 R45.2 R59.2 R75.1 S3.2 TP5.1 U1.8 U2.H1 U2.V9 U3.5 U3.6 U3.7 U9.8 U18.8 | length 3419.5
  Top Layer w8: R4.1@3728.57,4429.01 3748.07,4429.01 v1@3748.13,4428.95 ; v1(4371.44,4141.61) 4383.88,4129.17 C88.1@4383.88,4124.76 4383.88,4094.76 C102.1@4379.37,4090.24
  Top Layer w10: L2.1@2926.51,4256.95 2933.35,4250.1 3001.46,4250.1 U1.8@3035.15,4216.41 ; R19.2@3579.99,4338.56 3580.36,4338.92 3580.36,4360.55 v1(3580.83,4361.02) ; v1(3629.11,4145.27) 3641.28,4145.27 3647.9,4151.89 3659.99,4151.89 3671.7,4163.61 3671.7,4239.21 3669.91,4241 C126.1@3669.91,4262.91 3668.9,4261.9 3668.9,4275.32 3665.64,4278.59 U18.8@3665.64,4303.01 ; v1(3705.55,3883.32) 3709.73,3887.5 TP5.1@3709.73,3911.44 ; U2.H1@4009.24,3873.89 v1(4024.98,3889.64) ; U2.V9@4324.2,4125.86 v1(4339.94,4141.61) ; v1(4367.63,4410.91) 4378.13,4400.41 R5.1@4378.13,4385.29
  PWR2 w15: v1(4780.64,3983.52) 4983.52,3983.52 5009.96,4009.96 v1(5043.37,4009.96)
  PWR2 w20: 2738.56,4319.93 2696.76,4278.13 2696.76,4259.71 2678.29,4241.25 2678.29,4062.69 2828.75,3912.23 3062.72,3912.23 3076.91,3926.42 3386.61,3926.42 3404.99,3908.04 3557.89,3908.04 3565.87,3916.02 3635.97,3916.02 3668.8,3883.19 v1(3669.07,3883.19) ; v1@2879.98,4319.93 v1(2882.11,4317.81)
  Bottom Layer w5.5: v1(4182.46,3858.15) 4238.15,3858.15 4253.89,3873.89 4293.39,3873.89 ; R2.1@4295.7,4123.1 4321.43,4123.1 v1(4339.94,4141.61) 4324.2,4157.36 4324.2,4186.5 4329,4191.3 4329,4220.2 4324.44,4224.76 R59.2@4311.76,4224.76
  Bottom Layer w8: R43.2@3641.22,3875.43 3661.3,3875.43 v1(3669.07,3883.19) ; v1(3705.55,3883.32) 3705.55,3866.38 3710.23,3861.69 C100.1@3731.37,3861.69 U9.8@3731.37,3901.12 ; U3.5@3770.97,4252.67 3783.91,4252.67 U3.6@3783.91,4232.98 ; v1(3804.51,3952.63) 3819.73,3967.86 R45.2@3819.73,3978.91 ; 4293.39,3873.89 4303.2,3883.7 S3.2@4378.13,3883.7 ; R59.2@4311.76,4224.76 R23.2@4311.76,4249.29
  Bottom Layer w10: v1@3628.11,4145.27 3628.11,4126.02 3659.8,4094.33 3659.8,4073.39 ; v1@3629.11,4145.37 R40.1@3649.76,4145.37 ; R44.2@3629.89,4059.85 3646.26,4059.85 3659.8,4073.39 ; U3.7@3741.86,4203.87 3741.86,4182.84 3751.18,4173.52 ; U3.6@3770.97,4232.98 3783.91,4232.98 3783.91,4229.09 3785.88,4227.12 C2.2@3785.88,4180.75 3771.42,4180.75 3764.16,4173.52 3751.18,4173.52 ; C87.1@4008.95,3861.38 4009.74,3861.38 4011.04,3862.68 4011.04,3873.53 4024.98,3887.48 v1(4024.98,3889.64) ; R22.2@4329.48,4288.76 R21.2@4329.48,4310.76 4329.48,4322.94 4367.63,4361.09 v1(4367.63,4410.91) ; 3659.8,4073.39 3671.75,4061.44 3725.24,4061.44 3755.86,4092.07 3755.86,4104.82 3762.94,4111.9 C3.2@3762.94,4125.72 3742.56,4146.1 3742.56,4164.9 3751.18,4173.52
  Bottom Layer w15: R31.2@5023.3,4008.93 5023.67,4009.31 5041.9,4009.31 5042.56,4009.96 v1(5043.37,4009.96)
  other v1: 4777.34,3947.7 4780.6,3965.46 2883.69,4293.76 2920.71,4293.67 2902.82,4305.16 2922.3,4317.87 3748.13,4426.95
PMIC_CLK: R103.2 U1.3 | length 1504.5
  Top Layer w5.5: v1(3117,4280) 3136.53,4260.47 U1.3@3136.53,4216.41
  Sig1 w4.2: v1(3117,4280) 3149.9,4247.1 3199.96,4247.1 3212.53,4259.67 3534.53,4259.67 3569.25,4224.95 3569.25,4213.89 3608.54,4174.6 3622.66,4174.6 3643.82,4153.45 3657.93,4153.45 3669.03,4164.55 3669.03,4172.75 3722.74,4226.46 3773.24,4226.46 3798.17,4251.4 3810.85,4251.4 3819.81,4242.44 3819.81,4230.66 3829.67,4220.8 3842.35,4220.8 3843.05,4221.5 3920.94,4221.5 3941.13,4241.68 4226.25,4241.68 4237.56,4252.99 4356.92,4252.99 v1(4371.44,4267.52)
  Bottom Layer w5.5: R103.2@4365.65,4245.1 4365.65,4261.72 v1(4371.44,4267.52)
PMIC_EN1: R34.1 U1.7 | length 75.4
  Top Layer w5.5: R34.1@3012.8,4272.69 3013.58,4272.69 3040.26,4246.02 3040.26,4240.83 3057.79,4223.3 U1.7@3057.79,4216.41
PMIC_EN2: R35.1 U1.15 | length 48.4
  Top Layer w5.5: R35.1@3034.52,4028.04 3034.52,4029.38 3057.79,4052.64 U1.15@3057.79,4066.81
PMIC_EN3: R36.1 U1.2 | length 33.2
  Top Layer w5.5: U1.2@3156.21,4216.41 R36.1@3156.21,4249.57
PMIC_NINT: R26.1 U1.19 | length 43.1
  Top Layer w5.5: U1.19@3136.53,4066.81 3136.53,4038.87 3146.72,4028.68 R26.1@3146.72,4027.89
PMIC_NRST: R33.1 U1.20 | length 46.7
  Top Layer w5.5: U1.20@3156.21,4066.81 3156.21,4047.53 3175.06,4028.68 R33.1@3175.06,4027.89
PMIC_PGOOD: R25.1 U1.16 | length 43
  Top Layer w5.5: R25.1@3065.02,4029 3077.47,4041.45 U1.16@3077.47,4066.81
PMIC_SCL: R32.2 U1.5 | length 36.5
  Top Layer w5.5: R32.2@3094.52,4251.34 3094.52,4236 3097.68,4232.84 3097.68,4216.93 U1.5@3097.16,4216.41
PMIC_SDA: R28.2 U1.6 | length 35.8
  Top Layer w5.5: R28.2@3062.78,4245.55 3063.77,4245.55 3077.26,4232.06 3077.26,4216.63 U1.6@3077.47,4216.41
PMICVIO_3V3: R25.2 R26.2 R33.2 R34.2 R35.2 R36.2 R50.1 R52.2 | length 224.3
  Top Layer w10: R50.1@2845.2,4320.16 2845.2,4337.8 2861.97,4354.56 R52.2@2861.97,4355.35 2862.01,4355.31 v1(2885.5,4355.26) v1(2885.5,4355.26) v1(2885.5,4378.18) ; v1(2990.53,4289.37) 2990.53,4272.91 R34.2@2990.75,4272.69 ; v1(3012.52,4006.33) 3012.52,4007 R35.2@3034.52,4007 3034.57,4006.95 R25.2@3065.02,4006.95 ; R26.2@3146.72,4005.84 R33.2@3175.06,4005.84 3194.31,4005.84 v1(3194.72,4005.44) ; R36.2@3177.55,4249.27 3177.8,4249.52 v1(3177.8,4266.67)
PS0: R77.2 R93.1 U7.6 | length 62.7
  Bottom Layer w5.5: R77.2@5185.3,4010.48 R93.1@5206.3,4010.48 U7.6@5206.3,3968.74
PS1: R78.2 R98.1 U7.5 | length 75.6
  Bottom Layer w5.5: R78.2@5165.52,3984 R98.1@5165.52,3961 5180.42,3961 5187.49,3953.94 5187.49,3946.7 5197.44,3936.75 U7.5@5203.84,3936.75
RE: A1.1
  other v1: 7065.5,4448.37 7065.5,4617.37
RESETN: R94.1 U10.1 | length 51.4
  Bottom Layer w5.5: U10.1@5336.33,4473.35 5336.6,4473.63 5387.21,4473.63 R94.1@5387.48,4473.91
RF_N: C23.1 L6.1 U8.2 | length 139.8
  Top Layer w14.15: L6.1@6415.18,4377.75 6415.09,4377.66 C23.1@6415.09,4324.42 6415.09,4300.45 6431.96,4283.58 U8.2@6431.96,4244.97
RF_P: C22.2 L1.1 U8.1 | length 137.8
  Top Layer w14.15: U8.1@6451.65,4244.97 6451.65,4281.73 6468.52,4298.6 L1.1@6468.52,4324.41 C22.2@6468.51,4375.79
SENS_INT: R18.2 R100.1 U7.14 | length 396.1
  Bottom Layer w5.5: R100.1@5331,4350 5331,4348.2 5343.62,4335.58 5343.62,4335.52 5346.92,4332.22 5346.92,4026.35 5355.36,4017.91 5357.44,4017.91 5362.78,4012.57 R18.2@5362.78,4011.28 5363.28,4010.78 5363.28,3969.24 U7.14@5363.78,3968.74
SENS_NRST: R81.2 R97.2 U10.7 | length 383.9
  Bottom Layer w5.5: U10.7@5298.93,4402.48 5298.93,4328.94 5316.2,4311.66 5316.2,4208.88 5310.42,4203.1 5310.42,4131.34 5304.72,4125.64 R81.2@5304.72,4059.87 R97.2@5304.72,4030.51
SOP0: R159.2 S1.3 | length 1769.9
  Top Layer w5.5: v1(5505.37,4095.46) S1.3@5505.37,4135.46
  Sig1 w4.2: v1(4345.4,4058.9) 4412.22,4058.9 4417.07,4063.76 4522.39,4063.76 4532.65,4053.5 4566.87,4053.5 4623.84,4110.47 4713.27,4110.47 4723.49,4100.24 4740.28,4100.24 4796.81,4156.78 4796.81,4185.87 4908.57,4297.63 4938.52,4297.63 4970.5,4265.66 5021.81,4265.66 5093.84,4193.63 5093.84,4098.4 5122,4070.23 5322.69,4070.23 5366.86,4114.4 5486.43,4114.4 v1(5505.37,4095.46)
  Bottom Layer w5.5: R159.2@4223.5,4067.08 4225.4,4065.18 4225.4,4004.31 4229.83,3999.88 4351.98,3999.88 ; v1(4345.4,4058.9) 4345.4,4044.2 4360.8,4028.8 4360.8,4008.8 4351.98,3999.98
SOP1: R171.2 S1.4 | length 1755.7
  Top Layer w5.5: v1(5555.37,4095.46) S1.4@5555.37,4135.46
  Sig1 w4.2: v1(4245.46,3984.13) 4260.76,3999.43 4355.03,3999.43 4388.5,3965.96 4388.5,3950.96 4420.67,3918.79 4533.64,3918.79 4552.58,3937.72 4566.56,3937.72 4575.22,3946.38 4686.77,3946.38 4701.47,3961.08 4701.47,3972.47 4842.2,4113.2 4842.2,4168.43 4872.25,4198.48 4996.05,4198.48 5026.17,4228.6 5036.54,4228.6 5080.83,4184.31 5080.83,4098.03 5117.03,4061.83 5356.48,4061.83 5374.7,4080.05 5419.15,4080.05 5449.03,4050.16 5481.71,4050.16 5527.01,4095.46 v1(5555.37,4095.46)
  Bottom Layer w5.5: R171.2@4215.47,3980.18 4241.5,3980.18 v1(4245.46,3984.13)
SPI/CAN_MUX_CTRL: R118.1 S2.1 U13.15 | length 2264.7
  Top Layer w5.5: S2.1@5199.37,3773.46 5223.17,3749.66 v1(5223.17,3739.66) ; v1(6676.29,4411.48) R118.1@6696.81,4411.48 6703.33,4411.48 6721.06,4393.75 U13.15@6721.06,4370
  Sig1 w4.2: v1(5223.17,3739.66) 5425.03,3739.66 5468.08,3696.61 5693.38,3696.61 5771.25,3774.48 5880.03,3774.48 6062.15,3956.6 6148.5,3956.6 6154.07,3962.16 6210.28,3962.16 6250.52,4002.4 6737.52,4002.4 6791.96,4056.84 6791.96,4182.21 6764,4210.18 6764,4335.33 6727.24,4372.08 6715.69,4372.08 v1(6676.29,4411.48)
SPI_CLK1: R151.2 R160.2 R161.1 RA3.2 U13.8 | length 3952.6
  Top Layer w4.2: U13.8@6752.56,4275.51 6752.56,4258.25 6755.81,4255 v1(6779.81,4255)
  Top Layer w5.5: v1(4757.56,3832.95) 4757.56,3836.33 4764.81,3843.58 4764.81,3862.76 RA3.2@4765.06,3863.01 ; R161.1@6131.17,4158.46 6129.37,4158.46 6126.95,4156.04 6126.95,4154.24 6114.17,4141.46 v1(6114.17,4074.38) 6114.17,4029.08 6090.68,4005.59 6066.45,4005.59 6014.07,4057.97 6014.07,4264.22 v1(6157.61,4407.76)
  Sig1 w4.2: v1(4757.56,3832.95) 4757.56,3853.56 4899.05,3995.05 5036.64,3995.05 5041.08,3990.62 5366.57,3990.62 5404.33,3952.86 5579.17,3952.86 5742.09,4115.78 5742.09,4177.55 5830.73,4266.18 6085.54,4266.18 6106.34,4245.39 6106.34,4225.27 6089.82,4208.75 6050.17,4208.75 6032.38,4190.96 6032.38,4042.52 6055.36,4019.54 6087.27,4019.54 6114.17,4046.44 v1(6114.17,4074.38)
  Bottom Layer w4.2: v1(6114.17,4074.38) 6143.51,4045.04 6185.87,4045.04 6269.08,3961.83 6269.08,3939.58 6280.34,3928.32 R160.2@6280.34,3913.29
  Bottom Layer w5.5: v1(6114.17,4074.38) 6114.17,4147.39 6188.01,4221.24 6402.94,4221.24 6496.53,4314.82 6566.09,4314.82 6577.56,4303.35 6577.56,4286.15 6631.15,4232.56 6672.35,4232.56 6694.8,4255 v1(6779.81,4255) ; R151.2@6128.21,4348.48 6129,4348.48 6157.61,4377.09 v1(6157.61,4407.76)
SPI_CLK1_T: J6.1 R185.1 U14.2 | length 805.8
  Top Layer w5.5: J6.1@5623.32,3810.06 5629.35,3804.03 5629.35,3770.09 5677.2,3722.25 5761.82,3722.25 5794.59,3755.01 5917.56,3755.01 5935.34,3737.23 R185.1@5935.34,3722.49 6122.86,3722.49 6142.89,3742.51 6189.74,3742.51 6210.52,3721.73 6232.05,3721.73 v1(6248.28,3737.96)
  Bottom Layer w5.5: v1(6248.28,3737.96) 6256.79,3746.48 U14.2@6256.79,3799.77
SPI_CS1: R74.1 U13.11 | length 2443.5
  Top Layer w4.2: R74.1@4971.72,3922.44 4989.42,3922.44 4990.15,3923.17 v1(4990.56,3923.17)
  Top Layer w5.5: v1(6736.18,4330.63) U13.11@6760.43,4330.63
  Sig2 w4.2: v1(4990.56,3923.17) 4977.76,3935.97 4977.76,3952.49 4986.72,3961.45 5056.18,3961.45 5097.94,3919.69 5193.93,3919.69 5259.27,3854.35 5259.27,3821.95 5368.68,3712.53 5711.27,3712.53 5752.96,3754.22 5809.04,3754.22 5856.23,3707.04 6109.92,3707.04 6258.25,3855.37 6323.92,3855.37 6375.19,3906.64 6453.35,3906.64 6493.66,3946.95 6646.99,3946.95 6691.53,3991.5 6691.53,4310.99 6711.17,4330.63 v1@6735.18,4330.63
SPI_CS_MUX_CTRL: R104.1 S2.2 U11.6 | length 541.8
  Top Layer w5.5: U11.6@4918.45,3949.5 4928.95,3949.5 R104.1@4950.81,3971.36 4950.81,3972.14 4966.42,3987.75 4996.47,3987.75 5025.62,4016.9 5025.62,4017.32 5036.02,4027.71 5113.25,4027.71 5124.18,4016.78 5124.18,4014.64 5209.25,3929.57 5209.25,3902.24 5253.32,3858.17 5253.32,3777.41 S2.2@5249.37,3773.46
SPI_MISO1: R87.1 R154.1 R166.2 RA3.4 U13.1 | length 4196.6
  Top Layer w5.5: v1@4796.56,3838.48 RA3.4@4796.56,3863.01 ; v1(6078.56,4034.84) 6037.07,4076.34 6037.07,4242.05 6055.89,4260.86 6097.92,4260.86 6131.17,4227.62 R87.1@6131.17,4202.46 ; v1(6668.81,4354) 6676.43,4346.38 U13.1@6699.41,4346.38
  Sig1 w4.2: v1(4794.06,3838.48) 4794.06,3878.18 4902.53,3986.65 5033.16,3986.65 5042.04,3977.78 5366.93,3977.78 5423.63,3921.08 5560.35,3921.08 5748.57,4109.3 ; 5748.03,4109.84 5750.49,4112.3 5750.49,4158.89 5843.74,4252.14 6087.68,4252.14 6095.3,4244.52 6095.3,4226.12 6086.34,4217.15 6044.05,4217.15 6008.51,4181.62 6008.51,4043.1 6040.47,4011.14 6090.75,4011.14 6129.47,4049.86 6129.47,4090.65 6117.51,4102.6 ; v1(6078.56,4034.84) 6098.03,4054.31 6098.03,4083.13 6117.51,4102.6 ; v1(6668.81,4354) 6656.99,4342.17 6656.99,4284.19 6618.51,4245.72 6618.51,4222.63 6536.17,4140.29 6130.46,4140.29 6117.51,4127.34 6117.51,4102.6
  Sig2 w4.2: v1(5652.11,4310.12) 5652.11,4273.91 5674.74,4251.28 5844.6,4251.28 5906.43,4189.45 5906.43,4064.55 5936.14,4034.84 v1(6078.56,4034.84)
  Bottom Layer w4.2: v1@5655.55,4307.79 5651.69,4311.65 5665.4,4311.65 R154.1@5678.13,4298.93 ; v1(6078.56,4034.84) 6181.64,4034.84 6218.12,3998.37 6218.12,3937.9 6240.62,3915.4 R166.2@6240.62,3913.6
SPI_MISO1_T: J6.2 R184.1 U14.3 | length 733.9
  Top Layer w5.5: J6.2@5643.01,3810.06 5643.01,3777.52 5686.79,3733.75 5757.06,3733.75 5789.82,3766.51 5932.82,3766.51 R184.1@5953.35,3745.98 5953.35,3747.91 5969.05,3763.61 6052.93,3763.61 6062.24,3754.31 6202.24,3754.31 6217.06,3739.48 v1(6217.87,3739.48)
  Bottom Layer w5.5: v1(6217.87,3739.48) 6241.04,3762.65 U14.3@6241.04,3797.8
SPI_MOSI1: R86.1 R153.2 RA3.3 U13.4 | length 4898.1
  Top Layer w5.5: v1(4759.94,3802.97) 4778.81,3821.84 4778.81,3828.63 4776.31,3831.13 4776.31,3845.83 4780.12,3849.64 4780.12,3862.32 RA3.3@4780.81,3863.01 ; R86.1@6131.02,4180.57 6128.6,4178.15 6118.39,4178.15 6096.21,4155.96 6096.21,4042.3 6096.31,4042.19 6096.31,4027.49 6085.92,4017.09 6071.21,4017.09 6025.57,4062.73 6025.57,4251.24 6107.27,4332.95 6185.33,4332.95 6208.93,4356.55 6208.93,4437.78 v1(6220.67,4449.52) ; v1(6674.81,4288) 6674.81,4294.5 6679.45,4299.13 U13.4@6697.44,4299.13
  Sig2 w4.2: v1(4759.94,3802.97) 4790.4,3802.97 4810.84,3823.41 4828.46,3823.41 4881.01,3875.96 4949.19,3875.96 4955.33,3882.1 5096.83,3882.1 5213.6,3765.33 5291.42,3765.33 5361.01,3695.73 5718.26,3695.73 5724.87,3702.34 5759.95,3737.42 5802.09,3737.42 5849.27,3690.24 6116.88,3690.24 6265.21,3838.57 6330.88,3838.57 6368.33,3876.02 6476.62,3876.02 6625.22,3727.42 6625.22,3714.5 6657.93,3681.8 6787.43,3681.8 6837.43,3731.8 6837.43,3859.02 6837.58,3859.17 6837.58,3872.69 6837.43,3872.83 6837.43,3889.5 6808.83,3918.1 6808.83,4280.54 6742.79,4346.58 6699.16,4346.58 6674.81,4322.23 v1(6674.81,4288)
  Bottom Layer w5.5: v1(6220.67,4449.52) 6220.67,4430.18 6208.93,4418.43 6208.93,4366.97 6178.1,4336.14 6143.04,4336.14 6126.12,4319.22 R153.2@6126.12,4312.59 6126.12,4297.39 6187.43,4236.08 6401.52,4236.08 6491.77,4326.32 6570.85,4326.32 6608.43,4288.75 6674.06,4288.75 v1(6674.81,4288)
SRDY: R112.1 TP27.1 U8.31 | length 1600.9
  Top Layer w5.5: U8.31@6353.22,3977.25 6353.22,3963.19 v1(6366.18,3950.23)
  Sig2 w4.2: v1(5221.09,4348.53) 5221.09,4313.26 5262.96,4271.39 5303.92,4271.39 5471.47,4103.84 5471.47,4043.93 5496.63,4018.76 5496.63,3957.17 5573.95,3879.85 5656.7,3879.85 5689.63,3846.92 5988.75,3846.92 6039.75,3897.92 6226.58,3897.92 6248.74,3875.76 6277.12,3875.76 6351.59,3950.23 v1(6366.18,3950.23)
  Bottom Layer w5.5: TP27.1@5204,4368 5204,4365.62 v1(5221.09,4348.53) 5240.03,4367.46 R112.1@5249.35,4367.46
SW0: L2.2 R53.2 U1.10 | length 186.1
  Top Layer w10: 2995.53,4173.11 3007.34,4161.3 U1.10@3046.37,4161.3
  Top Layer w12: R53.2@2884.16,4188.59 2884.38,4188.82 2911.6,4188.82 L2.2@2926.51,4203.73 2957.13,4173.11 2995.53,4173.11
SW0_CAP: C31.1 R53.1 | length 27
  Top Layer w12: C31.1@2861.78,4207.42 2861.78,4207.56 2872.67,4218.45 2884.11,4218.45 R53.1@2884.16,4218.4
SW1: L3.2 R54.2 U1.12 | length 196.7
  Top Layer w10: 2995.53,4110.11 3007.34,4121.93 U1.12@3046.37,4121.93
  Top Layer w12: R54.2@2883.09,4090.26 2884.19,4089.16 2911.45,4089.16 L3.2@2927.23,4073.38 2931.2,4073.38 2947.93,4090.11 2947.93,4100.86 2957.18,4110.11 2995.53,4110.11
SW1_CAP: C32.1 R54.1 | length 24.6
  Top Layer w10: C32.1@2862.17,4065.44 2862.17,4063.64 2862.34,4063.47 2864.14,4063.47 2867.88,4059.73 2882.37,4059.73 R54.1@2883.09,4060.45
SW2: L4.2 R55.2 U1.25 | length 191.3
  Top Layer w10: U1.25@3167.63,4161.3 3206.66,4161.3 3218.47,4173.11
  Top Layer w12: 3218.47,4173.11 3258.77,4173.11 3266.19,4180.53 3266.19,4188.61 3282.91,4205.33 3298.12,4190.12 3328.87,4190.12 R55.2@3329.41,4189.59
SW2_CAP: C33.1 R55.1 | length 28.8
  Top Layer w10: R55.1@3329.41,4219.4 3329.82,4218.98 3342.38,4218.98 3352.15,4209.21 C33.1@3352.15,4207.41
SW3: L5.2 R56.2 U1.23 | length 192.5
  Top Layer w10: U1.23@3167.63,4121.93 3206.66,4121.93 3218.47,4110.11
  Top Layer w12: 3218.47,4110.11 3255.28,4110.11 3267.47,4097.92 3267.47,4092.23 3284.2,4075.51 L5.2@3288.17,4075.51 3303.26,4090.6 3330.73,4090.6 R56.2@3331.14,4091.01
SW3_CAP: C34.1 R56.1 | length 23.2
  Top Layer w10: R56.1@3331.14,4061.2 3332.55,4062.61 3352.31,4062.61 3352.48,4062.78 C34.1@3352.48,4064.02
UART_MUX_CTRL1: R19.1 S1.1 U18.1 U18.5 | length 2567.9
  Top Layer w5.5: R19.1@3579.99,4317.53 3581.47,4319.01 3591.57,4319.01 3602.16,4329.59 ; U18.5@3621.94,4329.59 3602.34,4329.59 3596.8,4335.13 3596.8,4343.01 3606.63,4352.85 3606.63,4387.15 3634.23,4414.75 3672.02,4414.75 3685.32,4401.45 U18.1@3685.32,4354.59 ; v1(5405.37,4095.46) S1.1@5405.37,4135.46
  Sig1 w4.2: v1(3685.37,4401.5) 3708.59,4378.28 4368.52,4378.28 4416.5,4426.26 4525.73,4426.26 4541.64,4442.17 4541.64,4492.34 4604.6,4555.3 4697.04,4555.3 4704.99,4547.35 4785.62,4547.35 4851.87,4613.6 5190.72,4613.6 v1(5220.59,4583.73)
  Sig2 w4.2: v1(5220.59,4583.73) 5202.12,4565.26 5202.12,4395.19 5197.39,4390.46 5197.39,4303.44 v1(5405.37,4095.46)
UART_MUX_CTRL2: R1.1 S1.2 U15.1 U15.5 | length 410.2
  Top Layer w5.5: v1(5455.37,4095.46) S1.2@5455.37,4135.46
  Bottom Layer w5.5: R1.1@5455.37,4116.98 v1(5455.37,4095.46) 5480.27,4095.46 5519.85,4055.88 U15.1@5519.85,4041.06 5533.74,4041.06 5544.84,4052.16 5567.81,4052.16 5588.6,4031.36 5588.6,3969.41 5579.5,3960.31 5539.89,3960.31 5533.16,3967.04 5496.43,3967.04 5493.27,3970.19 U15.5@5493.27,3976.1
USB_5V: FL2.1 J1.1
USB_5V_B: FL14.1 J5.1
USB_AR_RS232RX: U3.13 U18.4 | length 240.2
  Top Layer w4.2: v1(3623.36,4381.75) 3626.27,4378.85 U18.4@3626.27,4356.16
  Sig1 w4.2: v1(3585.2,4219.06) 3585.2,4220.6 3595.25,4230.65 3595.25,4353.64 v1(3623.36,4381.75)
  Bottom Layer w5.5: v1(3585.2,4219.06) 3599.13,4232.98 U3.13@3614.31,4232.98
USB_AR_RS232TX: U3.12 U18.2 | length 608.8
  Top Layer w5.5: v1(3646.73,4397.53) 3665.64,4378.63 U18.2@3665.64,4356.16
  Bottom Layer w5.5: U3.12@3643.43,4203.87 3643.43,4188.56 3608.33,4153.46 3608.33,4128.87 3571.32,4091.86 3545.32,4091.86 3530.24,4106.94 3530.24,4264.02 3568.5,4302.27 3568.5,4320.75 3599.09,4351.35 3599.09,4392.78 3611.65,4405.34 3638.93,4405.34 v1(3646.73,4397.53)
USB_DM: J1.2 R60.2 | length 1415.3
  Sig2 w4: v1(2703.29,4140.98) 2709.29,4146.98 2725.45,4146.98 2773.44,4099 3052.63,4099 3071.63,4080 3074.56,4077.07 3144.81,4077.07 3147.73,4080 3184.27,4116.54 3198.41,4130.68 3198.41,4154.23 3223.95,4179.77 3332.83,4179.77 3439.62,4286.57 3583.59,4286.57 3651.97,4354.96 3712.28,4354.96 3718.82,4361.5 3767.48,4410.16 3804.08,4410.16 v1@3823.87,4429.94
  Bottom Layer w4: v1(2703.29,4140.98) 2710.04,4147.73 2719.74,4147.73 2728.29,4139.19 J1.2@2747.66,4139.19 ; v1@3824.12,4430.19 3823.95,4430.03 3823.95,4424.78 3841.44,4407.29 3841.44,4392.31 3846.33,4387.42 R60.2@3846.82,4387.42
  other v1: 3824.12,4429.69
USB_DP: J1.3 R41.2 | length 1434.6
  Sig2 w4: v1(2703.29,4162.98) 2709.29,4156.98 2729.6,4156.98 2777.58,4109 3056.77,4109 3078.7,4087.07 3140.66,4087.07 3188.41,4134.82 3188.41,4158.38 3219.81,4189.77 3328.68,4189.77 3435.48,4296.57 3579.44,4296.57 3647.83,4364.96 3708.13,4364.96 3774.82,4431.64 3781.65,4431.64 3784.02,4429.27 3784.02,4422.57 3786.44,4420.16 3792.08,4420.16 v1@3801.87,4429.94
  Bottom Layer w4: v1(2703.29,4162.98) 2710.04,4156.23 2720.03,4156.23 2728.58,4164.78 J1.3@2747.66,4164.78 ; v1@3801.87,4429.94 3792.96,4421.03 3792.96,4416.74 3796.23,4413.48 3823.23,4413.48 3832.94,4403.77 3832.94,4395.05 R41.2@3825.31,4387.42 R41.2@3825.31,4390.31
  other v1: 3802.12,4429.69
VBUS: R64.2 R65.2 U3.8 | length 77.6
  Bottom Layer w10: R64.2@3715.38,4114.81 3715.38,4128.71 3718.57,4131.9 R65.2@3718.57,4143.04 3722.17,4146.64 U3.8@3722.17,4189.59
